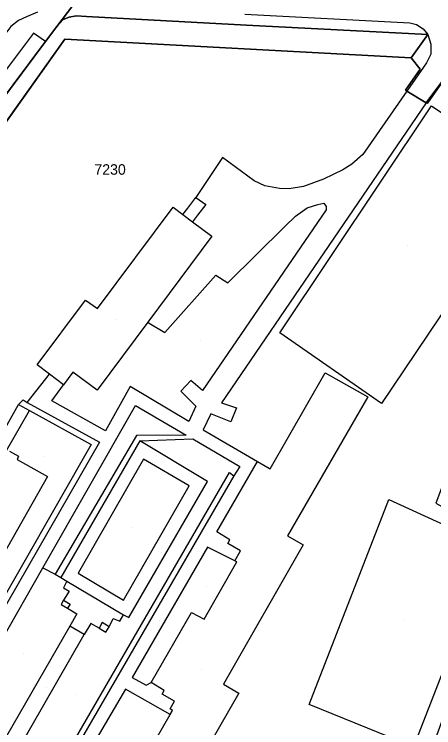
# Model space of a CAD drawing. Extents: x -266199 to -261993, y -1239047 to -1235108.
# Drawn here: x -263730.4 to -263650.7, y -1236600.9 to -1236465.2 of the extents above; entities that cross this region are included whole.
import ezdxf

# ---------------------------------------------------------------- set-up
doc = ezdxf.new("R2010")
doc.units = 0
for name, color, linetype in [('body_kn', 7, 'Continuous'), ('kladpar_druhypozemkov', 7, 'Continuous'), ('kladpar_hranice', 7, 'Continuous'), ('kladpar_parcelnecisla', 7, 'Continuous'), ('kladpar_plochy', 7, 'Continuous'), ('zappar_hrandruhpozemk', 7, 'Continuous')]:
    doc.layers.add(name, color=color, linetype=linetype)

msp = doc.modelspace()

# ---------------------------------------------------------------- linework, layer by layer
at = {"layer": 'body_kn'}
for p, q in [((-263718.63, -1236465.49), (-263718.63, -1236465.49)), ((-263716.71, -1236465.6), (-263716.71, -1236465.6)), ((-263729.61, -1236466.37), (-263729.61, -1236466.37)), ((-263728.1, -1236465.67), (-263728.1, -1236465.67)), ((-263721.1, -1236466.2), (-263721.1, -1236466.2)), ((-263719.96, -1236465.73), (-263719.96, -1236465.73)), ((-263655.24, -1236466.82), (-263655.24, -1236466.82)), ((-263722.34, -1236467.48), (-263722.34, -1236467.48)), ((-263686.28, -1236467.26), (-263686.28, -1236467.26)), ((-263653.95, -1236467.16), (-263653.95, -1236467.16)), ((-263652.72, -1236467.94), (-263652.72, -1236467.94)), ((-263726.77, -1236468.78), (-263726.77, -1236468.78)), ((-263651.85, -1236469), (-263651.85, -1236469)), ((-263651.85, -1236469), (-263651.85, -1236469)), ((-263724.51, -1236470.36), (-263724.51, -1236470.36)), ((-263724.51, -1236470.36), (-263724.51, -1236470.36)), ((-263720.79, -1236469.94), (-263720.79, -1236469.94)), ((-263651.22, -1236470.87), (-263651.22, -1236470.87)), ((-263655, -1236473.5), (-263655, -1236473.5)), ((-263655, -1236473.5), (-263655, -1236473.5)), ((-263651.26, -1236472.79), (-263651.26, -1236472.79)), ((-263652.06, -1236474.44), (-263652.06, -1236474.44)), ((-263653.26, -1236475.65), (-263653.26, -1236475.65)), ((-263656.07, -1236479.6), (-263656.07, -1236479.6)), ((-263655.84, -1236479.78), (-263655.84, -1236479.78)), ((-263655.84, -1236479.78), (-263655.84, -1236479.78)), ((-263652.12, -1236482.01), (-263652.12, -1236482.01)), ((-263652.12, -1236482.01), (-263652.12, -1236482.01)), ((-263651.91, -1236482.11), (-263651.91, -1236482.11)), ((-263651.12, -1236482.57), (-263651.12, -1236482.57)), ((-263690.86, -1236492.44), (-263690.86, -1236492.44)), ((-263664.2, -1236491.83), (-263664.2, -1236491.83)), ((-263666.26, -1236493.67), (-263666.26, -1236493.67)), ((-263668, -1236494.79), (-263668, -1236494.79)), ((-263671.66, -1236496.52), (-263671.66, -1236496.52)), ((-263684.82, -1236496.89), (-263684.82, -1236496.89)), ((-263682.8, -1236497.79), (-263682.8, -1236497.79)), ((-263675.47, -1236497.92), (-263675.47, -1236497.92)), ((-263679.99, -1236498.33), (-263679.99, -1236498.33)), ((-263678.2, -1236498.38), (-263678.2, -1236498.38)), ((-263695.89, -1236500.02), (-263695.89, -1236500.02)), ((-263695.89, -1236500.02), (-263695.89, -1236500.02)), ((-263700.25, -1236501.86), (-263700.25, -1236501.86)), ((-263697.44, -1236502.03), (-263697.44, -1236502.03)), ((-263694.02, -1236501.33), (-263694.02, -1236501.33)), ((-263674.76, -1236501.98), (-263674.76, -1236501.98)), ((-263672.74, -1236501.38), (-263672.74, -1236501.38)), ((-263671.57, -1236501.13), (-263671.57, -1236501.13)), ((-263671.17, -1236501.75), (-263671.17, -1236501.75)), ((-263698.41, -1236503.24), (-263698.41, -1236503.24)), ((-263698.41, -1236503.24), (-263698.41, -1236503.24)), ((-263695.61, -1236503.4), (-263695.61, -1236503.4)), ((-263676.98, -1236503.58), (-263676.98, -1236503.58)), ((-263671.14, -1236502.36), (-263671.14, -1236502.36)), ((-263696.53, -1236504.65), (-263696.53, -1236504.65)), ((-263696.53, -1236504.65), (-263696.53, -1236504.65)), ((-263678.99, -1236505.54), (-263678.99, -1236505.54)), ((-263692.85, -1236507.41), (-263692.85, -1236507.41)), ((-263692.13, -1236514.8), (-263692.13, -1236514.8)), ((-263689.84, -1236516.27), (-263689.84, -1236516.27)), ((-263716.85, -1236519.53), (-263716.85, -1236519.53)), ((-263714.61, -1236521.16), (-263714.61, -1236521.16)), ((-263705.04, -1236523.75), (-263705.04, -1236523.75)), ((-263705.04, -1236523.75), (-263705.04, -1236523.75)), ((-263704.78, -1236523.91), (-263704.78, -1236523.91)), ((-263701.79, -1236525.71), (-263701.79, -1236525.71)), ((-263701.79, -1236525.71), (-263701.79, -1236525.71)), ((-263679.97, -1236525.75), (-263679.97, -1236525.75)), ((-263726.06, -1236531.88), (-263726.06, -1236531.88)), ((-263726.06, -1236531.88), (-263726.06, -1236531.88)), ((-263719.28, -1236533.26), (-263719.28, -1236533.26)), ((-263671.31, -1236533.4), (-263671.31, -1236533.4)), ((-263671.31, -1236533.4), (-263671.31, -1236533.4)), ((-263723.75, -1236533.64), (-263723.75, -1236533.64)), ((-263723.75, -1236533.64), (-263723.75, -1236533.64)), ((-263696.85, -1236534.82), (-263696.85, -1236534.82)), ((-263721.09, -1236535.66), (-263721.09, -1236535.66)), ((-263708.36, -1236535.95), (-263708.36, -1236535.95)), ((-263714.68, -1236536.68), (-263714.68, -1236536.68)), ((-263698.79, -1236536.83), (-263698.79, -1236536.83)), ((-263694.67, -1236536.74), (-263694.67, -1236536.74)), ((-263728.73, -1236538.49), (-263728.73, -1236538.49)), ((-263723.29, -1236538.72), (-263723.29, -1236538.72)), ((-263663.23, -1236537.95), (-263663.23, -1236537.95)), ((-263729.6, -1236539.38), (-263729.6, -1236539.38)), ((-263729.6, -1236539.38), (-263729.6, -1236539.38)), ((-263727.95, -1236539.01), (-263727.95, -1236539.01)), ((-263727.95, -1236539.01), (-263727.95, -1236539.01)), ((-263707.38, -1236539.6), (-263707.38, -1236539.6)), ((-263695.91, -1236539.69), (-263695.91, -1236539.69)), ((-263691.06, -1236539.09), (-263691.06, -1236539.09)), ((-263688.16, -1236540.04), (-263688.16, -1236540.04)), ((-263660.65, -1236539.21), (-263660.65, -1236539.21)), ((-263727.55, -1236540.51), (-263727.55, -1236540.51)), ((-263693.09, -1236541.19), (-263693.09, -1236541.19)), ((-263697.23, -1236542.61), (-263697.23, -1236542.61)), ((-263689.23, -1236542.68), (-263689.23, -1236542.68)), ((-263694.51, -1236544.2), (-263694.51, -1236544.2)), ((-263713.1, -1236544.43), (-263713.1, -1236544.43)), ((-263707.19, -1236545.26), (-263707.19, -1236545.26)), ((-263697.77, -1236545.25), (-263697.77, -1236545.25)), ((-263715.83, -1236546.97), (-263715.83, -1236546.97)), ((-263714.23, -1236546.55), (-263714.23, -1236546.55)), ((-263706.58, -1236546.28), (-263706.58, -1236546.28)), ((-263706.58, -1236546.28), (-263706.58, -1236546.28)), ((-263696.46, -1236545.93), (-263696.46, -1236545.93)), ((-263696.46, -1236545.93), (-263696.46, -1236545.93)), ((-263729.61, -1236549.24), (-263729.61, -1236549.24)), ((-263729.85, -1236549.85), (-263729.85, -1236549.85)), ((-263705.85, -1236549.79), (-263705.85, -1236549.79)), ((-263684.22, -1236550.26), (-263684.22, -1236550.26)), ((-263684.22, -1236550.26), (-263684.22, -1236550.26)), ((-263689.54, -1236552.3), (-263689.54, -1236552.3)), ((-263687.54, -1236551.21), (-263687.54, -1236551.21)), ((-263681.8, -1236551.61), (-263681.8, -1236551.61)), ((-263724.08, -1236553.1), (-263724.08, -1236553.1)), ((-263688.67, -1236552.98), (-263688.67, -1236552.98)), ((-263688.67, -1236552.98), (-263688.67, -1236552.98)), ((-263697.15, -1236554.87), (-263697.15, -1236554.87)), ((-263693.72, -1236554.02), (-263693.72, -1236554.02)), ((-263659.2, -1236557.44), (-263659.2, -1236557.44)), ((-263659.2, -1236557.44), (-263659.2, -1236557.44)), ((-263691.91, -1236563.59), (-263691.91, -1236563.59)), ((-263678.48, -1236564.39), (-263678.48, -1236564.39)), ((-263689.86, -1236565.83), (-263689.86, -1236565.83)), ((-263689.44, -1236565.11), (-263689.44, -1236565.11)), ((-263693.68, -1236566.52), (-263693.68, -1236566.52)), ((-263687.42, -1236567.24), (-263687.42, -1236567.24)), ((-263675.53, -1236566.08), (-263675.53, -1236566.08)), ((-263688.49, -1236569.09), (-263688.49, -1236569.09)), ((-263688.49, -1236569.09), (-263688.49, -1236569.09)), ((-263688.11, -1236569.32), (-263688.11, -1236569.32)), ((-263724.97, -1236570.46), (-263724.97, -1236570.46)), ((-263724.97, -1236570.46), (-263724.97, -1236570.46)), ((-263718.29, -1236571.44), (-263718.29, -1236571.44)), ((-263722.64, -1236571.64), (-263722.64, -1236571.64)), ((-263721.58, -1236572.27), (-263721.58, -1236572.27)), ((-263721.58, -1236572.27), (-263721.58, -1236572.27)), ((-263720.42, -1236573.01), (-263720.42, -1236573.01)), ((-263720.42, -1236573.01), (-263720.42, -1236573.01)), ((-263721.07, -1236574.24), (-263721.07, -1236574.24)), ((-263719.98, -1236574.9), (-263719.98, -1236574.9)), ((-263721.03, -1236576.59), (-263721.03, -1236576.59)), ((-263721.03, -1236576.59), (-263721.03, -1236576.59)), ((-263709.65, -1236576.6), (-263709.65, -1236576.6)), ((-263709.65, -1236576.6), (-263709.65, -1236576.6)), ((-263721.49, -1236577.44), (-263721.49, -1236577.44)), ((-263720.31, -1236578.1), (-263720.31, -1236578.1)), ((-263720.31, -1236578.1), (-263720.31, -1236578.1)), ((-263719.81, -1236577.34), (-263719.81, -1236577.34)), ((-263718.54, -1236579.21), (-263718.54, -1236579.21)), ((-263709.65, -1236579.37), (-263709.65, -1236579.37)), ((-263696.74, -1236578.95), (-263696.74, -1236578.95)), ((-263696.74, -1236578.95), (-263696.74, -1236578.95)), ((-263713.7, -1236580.84), (-263713.7, -1236580.84)), ((-263711.6, -1236580.1), (-263711.6, -1236580.1)), ((-263710.35, -1236580.59), (-263710.35, -1236580.59)), ((-263708.65, -1236579.89), (-263708.65, -1236579.89)), ((-263708.65, -1236579.89), (-263708.65, -1236579.89)), ((-263694.33, -1236580.22), (-263694.33, -1236580.22)), ((-263694.33, -1236580.22), (-263694.33, -1236580.22)), ((-263719.83, -1236581.53), (-263719.83, -1236581.53)), ((-263719.83, -1236581.53), (-263719.83, -1236581.53)), ((-263715.89, -1236581.04), (-263715.89, -1236581.04)), ((-263714.26, -1236581.9), (-263714.26, -1236581.9)), ((-263714.26, -1236581.9), (-263714.26, -1236581.9)), ((-263712.41, -1236581.66), (-263712.41, -1236581.66)), ((-263712.41, -1236581.66), (-263712.41, -1236581.66)), ((-263717.12, -1236583.16), (-263717.12, -1236583.16)), ((-263713.03, -1236582.71), (-263713.03, -1236582.71)), ((-263713.03, -1236582.71), (-263713.03, -1236582.71)), ((-263708.02, -1236591.33), (-263708.02, -1236591.33)), ((-263705.35, -1236592.79), (-263705.35, -1236592.79)), ((-263704.42, -1236592.28), (-263704.42, -1236592.28)), ((-263704.42, -1236592.28), (-263704.42, -1236592.28)), ((-263690.67, -1236592.58), (-263690.67, -1236592.58)), ((-263709.28, -1236593.5), (-263709.28, -1236593.5)), ((-263702.29, -1236594.5), (-263702.29, -1236594.5)), ((-263701.91, -1236593.79), (-263701.91, -1236593.79)), ((-263687.72, -1236594.27), (-263687.72, -1236594.27)), ((-263699.96, -1236595.83), (-263699.96, -1236595.83)), ((-263674.38, -1236596.44), (-263674.38, -1236596.44)), ((-263700.8, -1236598.34), (-263700.8, -1236598.34)), ((-263700.8, -1236598.34), (-263700.8, -1236598.34)), ((-263700.79, -1236597.28), (-263700.79, -1236597.28)), ((-263700.35, -1236597.56), (-263700.35, -1236597.56))]:
    msp.add_line(p, q, dxfattribs=at)
at = {"layer": 'kladpar_druhypozemkov'}
for p, q in [((-263711.68, -1236493.61), (-263711.68, -1236493.61)), ((-263655.77, -1236509.11), (-263655.77, -1236509.11)), ((-263681.6, -1236522.1), (-263681.6, -1236522.1)), ((-263710.91, -1236523.26), (-263710.91, -1236523.26)), ((-263694.98, -1236527.28), (-263694.98, -1236527.28)), ((-263724.67, -1236549.25), (-263724.67, -1236549.25)), ((-263708.05, -1236562.86), (-263708.05, -1236562.86)), ((-263702.4, -1236567.5), (-263702.4, -1236567.5)), ((-263693.97, -1236573.99), (-263693.97, -1236573.99)), ((-263702.79, -1236580.49), (-263702.79, -1236580.49)), ((-263656.23, -1236580.49), (-263656.23, -1236580.49)), ((-263728.69, -1236586.68), (-263728.69, -1236586.68)), ((-263694.82, -1236589.85), (-263694.82, -1236589.85)), ((-263724.21, -1236593.25), (-263724.21, -1236593.25)), ((-263718.8, -1236594.56), (-263718.8, -1236594.56))]:
    msp.add_line(p, q, dxfattribs=at)
at = {"layer": 'kladpar_hranice'}
for points in [[(-263719.3, -1236463.54), (-263722.34, -1236467.48), (-263724.51, -1236470.36), (-263751.17, -1236506.09)], [(-263655, -1236473.5), (-263651.85, -1236469), (-263686.28, -1236467.26), (-263716.71, -1236465.6), (-263718.63, -1236465.49), (-263719.96, -1236465.73), (-263721.1, -1236466.2), (-263722.34, -1236467.48), (-263719.3, -1236463.54)], [(-263524.5, -1236462.92), (-263525.44, -1236474.41), (-263525.13, -1236478.12), (-263525.75, -1236476.92), (-263527.31, -1236475.67), (-263529.4, -1236475.19), (-263532.17, -1236474.97), (-263554.68, -1236473.85), (-263559.32, -1236473.51), (-263582.09, -1236472.17), (-263592.26, -1236472.04), (-263615.33, -1236470.89), (-263641.09, -1236468.33), (-263642.36, -1236469.45), (-263645.5, -1236474.26), (-263647.44, -1236475.73), (-263651.91, -1236482.11), (-263652.12, -1236482.01), (-263655.84, -1236479.78), (-263656.07, -1236479.6), (-263653.26, -1236475.65), (-263655, -1236473.5)], [(-263751.17, -1236506.09), (-263724.51, -1236470.36), (-263722.34, -1236467.48), (-263721.1, -1236466.2), (-263719.96, -1236465.73), (-263718.63, -1236465.49), (-263716.71, -1236465.6), (-263686.28, -1236467.26), (-263651.85, -1236469)], [(-263651.85, -1236469), (-263655, -1236473.5), (-263720.79, -1236469.94), (-263745.77, -1236505)], [(-263745.77, -1236505), (-263720.79, -1236469.94), (-263655, -1236473.5), (-263653.26, -1236475.65), (-263656.07, -1236479.6), (-263655.84, -1236479.78), (-263652.12, -1236482.01), (-263651.91, -1236482.11), (-263647.44, -1236475.73), (-263645.5, -1236474.26), (-263626.44, -1236475.66), (-263626.33, -1236476.45), (-263628.77, -1236485.94), (-263628.88, -1236488.15), (-263626.15, -1236491.73), (-263625.65, -1236494.26), (-263634.41, -1236515.37), (-263635.09, -1236517.76), (-263650.28, -1236558.18), (-263636.73, -1236565.67), (-263652.65, -1236609.13)]]:
    msp.add_lwpolyline(points, dxfattribs=at)
at = {"layer": 'kladpar_plochy'}
for p, q in [((-263719.96, -1236465.73), (-263718.63, -1236465.49)), ((-263718.63, -1236465.49), (-263716.71, -1236465.6)), ((-263716.71, -1236465.6), (-263686.28, -1236467.26)), ((-263722.34, -1236467.48), (-263721.1, -1236466.2)), ((-263721.1, -1236466.2), (-263719.96, -1236465.73)), ((-263724.51, -1236470.36), (-263722.34, -1236467.48)), ((-263686.28, -1236467.26), (-263651.85, -1236469)), ((-263651.85, -1236469), (-263655, -1236473.5)), ((-263751.17, -1236506.09), (-263724.51, -1236470.36)), ((-263720.79, -1236469.94), (-263745.77, -1236505)), ((-263655, -1236473.5), (-263720.79, -1236469.94))]:
    msp.add_line(p, q, dxfattribs=at)
for points in [[(-263719.3, -1236463.54), (-263722.34, -1236467.48), (-263724.51, -1236470.36), (-263751.17, -1236506.09)], [(-263647.44, -1236475.73), (-263651.91, -1236482.11), (-263652.12, -1236482.01), (-263655.84, -1236479.78), (-263656.07, -1236479.6), (-263653.26, -1236475.65), (-263655, -1236473.5), (-263651.85, -1236469), (-263686.28, -1236467.26), (-263716.71, -1236465.6), (-263718.63, -1236465.49), (-263719.96, -1236465.73), (-263721.1, -1236466.2), (-263722.34, -1236467.48), (-263719.3, -1236463.54)], [(-263745.77, -1236505), (-263720.79, -1236469.94), (-263655, -1236473.5), (-263653.26, -1236475.65), (-263656.07, -1236479.6), (-263655.84, -1236479.78), (-263652.12, -1236482.01), (-263651.91, -1236482.11), (-263647.44, -1236475.73), (-263645.5, -1236474.26), (-263626.44, -1236475.66), (-263626.33, -1236476.45), (-263628.77, -1236485.94), (-263628.88, -1236488.15), (-263626.15, -1236491.73), (-263625.65, -1236494.26), (-263634.41, -1236515.37), (-263635.09, -1236517.76), (-263650.28, -1236558.18), (-263636.73, -1236565.67), (-263652.65, -1236609.13)]]:
    msp.add_lwpolyline(points, dxfattribs=at)
at = {"layer": 'zappar_hrandruhpozemk'}
for p, q in [((-263725.98, -1236464.78), (-263728.1, -1236465.67)), ((-263686.57, -1236465.16), (-263655.24, -1236466.82)), ((-263726.77, -1236468.78), (-263752.27, -1236502.68)), ((-263724.51, -1236470.36), (-263726.77, -1236468.78)), ((-263651.26, -1236472.79), (-263652.06, -1236474.44)), ((-263652.06, -1236474.44), (-263655.84, -1236479.78)), ((-263655.84, -1236479.78), (-263664.2, -1236491.83)), ((-263652.12, -1236482.01), (-263691.06, -1236539.09)), ((-263664.2, -1236491.83), (-263666.26, -1236493.67)), ((-263631.52, -1236495.85), (-263660.65, -1236539.21)), ((-263698.41, -1236503.24), (-263696.53, -1236504.65)), ((-263671.14, -1236502.36), (-263694.67, -1236536.74)), ((-263701.79, -1236525.71), (-263692.13, -1236514.8)), ((-263726.06, -1236531.88), (-263716.85, -1236519.53)), ((-263705.04, -1236523.75), (-263714.68, -1236536.68)), ((-263723.75, -1236533.64), (-263726.06, -1236531.88)), ((-263681.8, -1236551.61), (-263671.31, -1236533.4)), ((-263671.31, -1236533.4), (-263663.23, -1236537.95)), ((-263727.95, -1236539.01), (-263723.75, -1236533.64)), ((-263723.29, -1236538.72), (-263721.09, -1236535.66)), ((-263713.1, -1236544.43), (-263723.29, -1236538.72)), ((-263663.23, -1236537.95), (-263678.48, -1236564.39)), ((-263727.95, -1236539.01), (-263714.23, -1236546.55)), ((-263691.06, -1236539.09), (-263688.16, -1236540.04)), ((-263707.19, -1236545.26), (-263722.64, -1236571.64)), ((-263714.23, -1236546.55), (-263741.11, -1236593.39)), ((-263706.58, -1236546.28), (-263721.58, -1236572.27)), ((-263706.58, -1236546.28), (-263696.46, -1236545.93)), ((-263696.46, -1236545.93), (-263687.54, -1236551.21)), ((-263691.91, -1236563.59), (-263684.22, -1236550.26)), ((-263684.22, -1236550.26), (-263681.8, -1236551.61)), ((-263723.68, -1236611.29), (-263689.54, -1236552.3)), ((-263689.54, -1236552.3), (-263688.67, -1236552.98)), ((-263687.54, -1236551.21), (-263688.67, -1236552.98)), ((-263724.08, -1236553.1), (-263742.2, -1236584.9)), ((-263688.67, -1236552.98), (-263722.84, -1236611.84)), ((-263709.65, -1236576.6), (-263697.15, -1236554.87)), ((-263674.38, -1236596.44), (-263659.2, -1236557.44)), ((-263694.33, -1236580.22), (-263688.11, -1236569.32)), ((-263688.11, -1236569.32), (-263688.49, -1236569.09)), ((-263720.42, -1236573.01), (-263709.65, -1236579.37)), ((-263721.03, -1236576.59), (-263719.81, -1236577.34)), ((-263719.81, -1236577.34), (-263720.31, -1236578.1)), ((-263704.42, -1236592.28), (-263696.74, -1236578.95)), ((-263696.74, -1236578.95), (-263694.33, -1236580.22)), ((-263713.7, -1236580.84), (-263714.26, -1236581.9)), ((-263712.41, -1236581.66), (-263713.7, -1236580.84)), ((-263714.26, -1236581.9), (-263713.03, -1236582.71)), ((-263713.03, -1236582.71), (-263712.41, -1236581.66)), ((-263687.72, -1236594.27), (-263702.95, -1236620.72))]:
    msp.add_line(p, q, dxfattribs=at)
for points in [[(-263728.1, -1236465.67), (-263729.61, -1236466.37), (-263731.04, -1236467.5), (-263732.2, -1236469.01)], [(-263655.24, -1236466.82), (-263653.95, -1236467.16), (-263652.72, -1236467.94), (-263651.85, -1236469), (-263651.22, -1236470.87), (-263651.26, -1236472.79)], [(-263652.12, -1236482.01), (-263647.44, -1236475.73), (-263644.64, -1236471.48)], [(-263660.65, -1236539.21), (-263679.97, -1236525.75), (-263651.12, -1236482.57), (-263631.52, -1236495.85)], [(-263666.26, -1236493.67), (-263668, -1236494.79), (-263671.66, -1236496.52), (-263675.47, -1236497.92), (-263678.2, -1236498.38), (-263679.99, -1236498.33), (-263682.8, -1236497.79), (-263684.82, -1236496.89), (-263690.86, -1236492.44), (-263695.89, -1236500.02)], [(-263698.41, -1236503.24), (-263697.44, -1236502.03), (-263695.89, -1236500.02)], [(-263695.89, -1236500.02), (-263694.02, -1236501.33), (-263695.61, -1236503.4), (-263696.53, -1236504.65)], [(-263716.85, -1236519.53), (-263714.61, -1236521.16), (-263700.25, -1236501.86), (-263698.41, -1236503.24)], [(-263692.13, -1236514.8), (-263689.84, -1236516.27), (-263678.99, -1236505.54), (-263676.98, -1236503.58), (-263674.76, -1236501.98), (-263672.74, -1236501.38), (-263671.57, -1236501.13), (-263671.17, -1236501.75), (-263671.14, -1236502.36)], [(-263696.53, -1236504.65), (-263692.85, -1236507.41), (-263705.04, -1236523.75)], [(-263705.04, -1236523.75), (-263704.78, -1236523.91), (-263701.79, -1236525.71)], [(-263714.68, -1236536.68), (-263719.28, -1236533.26), (-263721.09, -1236535.66), (-263723.75, -1236533.64)], [(-263694.67, -1236536.74), (-263696.85, -1236534.82), (-263698.79, -1236536.83), (-263695.91, -1236539.69), (-263697.23, -1236542.61), (-263708.36, -1236535.95), (-263713.1, -1236544.43)], [(-263729.6, -1236539.38), (-263728.73, -1236538.49), (-263727.95, -1236539.01)], [(-263735.52, -1236549.87), (-263729.6, -1236539.38), (-263727.55, -1236540.51)], [(-263724.97, -1236570.46), (-263707.38, -1236539.6), (-263697.77, -1236545.25), (-263707.19, -1236545.26)], [(-263688.16, -1236540.04), (-263689.23, -1236542.68), (-263693.09, -1236541.19), (-263694.51, -1236544.2), (-263684.22, -1236550.26)], [(-263732.16, -1236548.58), (-263727.55, -1236540.51), (-263715.83, -1236546.97), (-263741.95, -1236592.78)], [(-263708.65, -1236579.89), (-263693.72, -1236554.02), (-263706.58, -1236546.28)], [(-263731.3, -1236548.29), (-263729.61, -1236549.24), (-263729.85, -1236549.85), (-263724.08, -1236553.1)], [(-263697.15, -1236554.87), (-263705.85, -1236549.79), (-263718.29, -1236571.44), (-263709.65, -1236576.6)], [(-263659.2, -1236557.44), (-263639.69, -1236566.39), (-263654.54, -1236604.46), (-263674.38, -1236596.44)], [(-263688.49, -1236569.09), (-263687.42, -1236567.24), (-263689.86, -1236565.83), (-263689.44, -1236565.11), (-263691.91, -1236563.59)], [(-263678.48, -1236564.39), (-263675.53, -1236566.08), (-263690.67, -1236592.58), (-263687.72, -1236594.27)], [(-263688.49, -1236569.09), (-263693.68, -1236566.52), (-263708.02, -1236591.33), (-263705.35, -1236592.79), (-263704.42, -1236592.28)], [(-263739.31, -1236595.55), (-263724.97, -1236570.46), (-263722.64, -1236571.64), (-263721.58, -1236572.27)], [(-263721.58, -1236572.27), (-263720.42, -1236573.01), (-263721.07, -1236574.24), (-263719.98, -1236574.9), (-263721.03, -1236576.59)], [(-263721.03, -1236576.59), (-263721.49, -1236577.44), (-263720.31, -1236578.1)], [(-263720.31, -1236578.1), (-263718.54, -1236579.21), (-263719.83, -1236581.53)], [(-263712.41, -1236581.66), (-263711.6, -1236580.1), (-263710.35, -1236580.59), (-263709.65, -1236579.37), (-263708.65, -1236579.89)], [(-263719.83, -1236581.53), (-263731.9, -1236602.47), (-263739.31, -1236595.55), (-263739.86, -1236596.12)], [(-263729.73, -1236605.14), (-263717.12, -1236583.16), (-263719.83, -1236581.53)], [(-263714.26, -1236581.9), (-263715.89, -1236581.04), (-263717.12, -1236583.16)], [(-263700.8, -1236598.34), (-263700.35, -1236597.56), (-263700.79, -1236597.28), (-263699.96, -1236595.83), (-263702.29, -1236594.5), (-263701.91, -1236593.79), (-263704.42, -1236592.28)], [(-263700.8, -1236598.34), (-263709.28, -1236593.5), (-263721.92, -1236615.15)], [(-263708.81, -1236606.7), (-263706.35, -1236608.06), (-263700.8, -1236598.34)]]:
    msp.add_lwpolyline(points, dxfattribs=at)

# ---------------------------------------------------------------- texts
at = {"layer": 'kladpar_parcelnecisla'}
msp.add_text('7230', height=2, dxfattribs=at).set_placement((-263715.18, -1236495.7))

doc.saveas('drawing.dxf')
